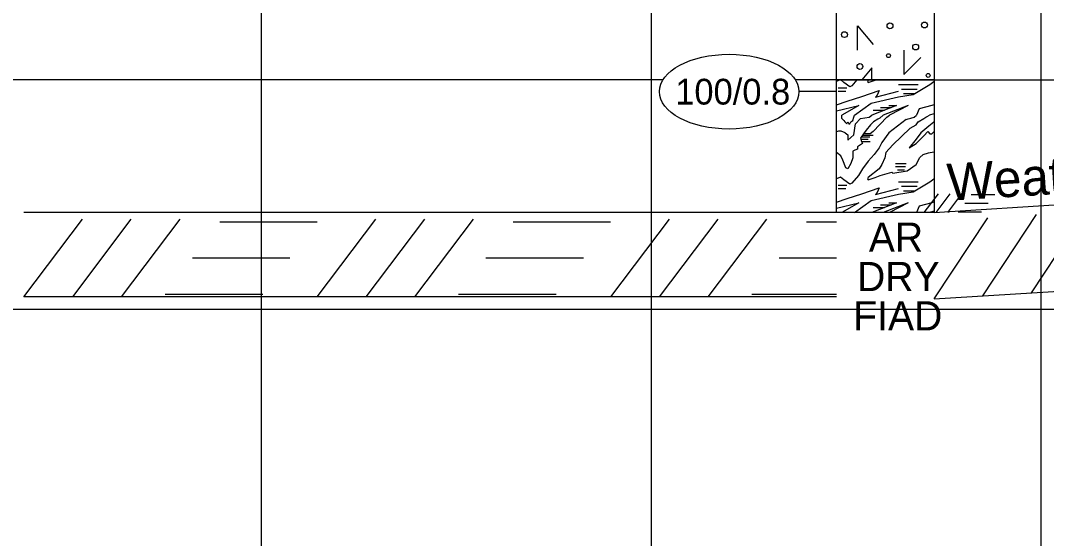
# Model space of a CAD drawing. Extents: x 278618 to 280654, y 171155 to 171855.
# Drawn here: x 280460.51 to 280486.82, y 171231.86 to 171245.16 of the extents above; entities that cross this region are included whole.
import ezdxf

# ---------------------------------------------------------------- set-up
doc = ezdxf.new("R2010")
doc.units = 0
for name, color, linetype in [('Prop Road Sect_ Boring - Material (Outline)', 7, 'Continuous'), ('Prop Road Sect_ Boring - Peripheral (HR Indicator)', 7, 'Continuous'), ('Prop Road Sect_ Boring - Peripheral (SPT Oval + Leader)', 7, 'Continuous'), ('Prop Road Sect_ Boring - Peripheral (SPT Tx)', 7, 'Continuous'), ('Prop Road Sect_ Material - Contact (General - Major)', 7, 'Continuous'), ('Prop Road Sect_ Material - Tx (Composite Desc)', 7, 'Continuous'), ('Prop Strc Sect_ Grid - minor', 7, 'Continuous'), ('Water Mark (Dry) Cell', 7, 'Continuous')]:
    doc.layers.add(name, color=color, linetype=linetype)

msp = doc.modelspace()

# ---------------------------------------------------------------- linework, layer by layer
at = {"layer": 'Prop Road Sect_ Boring - Material (Outline)'}
for p, q in [((280481.523, 171243.633), (280481.439, 171243.59)), ((280481.523, 171243.633), (280481.439, 171243.59)), ((280481.628, 171243.569), (280481.544, 171243.633)), ((280481.628, 171243.569), (280481.544, 171243.633)), ((280483.939, 171243.591), (280483.937, 171243.59)), ((280483.939, 171243.591), (280483.937, 171243.59)), ((280481.478, 171243.428), (280481.703, 171243.428)), ((280481.478, 171243.428), (280481.703, 171243.428)), ((280481.478, 171243.344), (280481.678, 171243.344)), ((280481.478, 171243.344), (280481.678, 171243.344)), ((280483.028, 171243.513), (280483.528, 171243.513)), ((280483.028, 171243.513), (280483.528, 171243.513)), ((280483.103, 171243.4), (280483.503, 171243.4)), ((280483.103, 171243.4), (280483.503, 171243.4)), ((280483.153, 171243.288), (280483.428, 171243.288)), ((280483.153, 171243.288), (280483.428, 171243.288)), ((280481.439, 171242.837), (280482.008, 171242.974)), ((280481.439, 171242.837), (280482.008, 171242.974)), ((280482.008, 171242.974), (280481.578, 171242.73)), ((280482.008, 171242.974), (280481.578, 171242.73)), ((280482.979, 171242.977), (280482.339, 171242.73)), ((280482.979, 171242.977), (280482.339, 171242.73)), ((280482.378, 171242.856), (280482.664, 171242.856)), ((280482.378, 171242.856), (280482.664, 171242.856)), ((280482.562, 171242.924), (280482.842, 171242.924)), ((280482.562, 171242.924), (280482.842, 171242.924)), ((280483.274, 171242.977), (280482.634, 171242.73)), ((280483.274, 171242.977), (280482.634, 171242.73)), ((280482.779, 171242.977), (280482.979, 171242.977)), ((280482.779, 171242.977), (280482.979, 171242.977)), ((280483.274, 171242.977), (280482.796, 171242.73)), ((280483.274, 171242.977), (280482.796, 171242.73)), ((280483.937, 171242.995), (280483.939, 171242.996)), ((280483.937, 171242.995), (280483.939, 171242.996)), ((280483.937, 171242.837), (280483.939, 171242.838)), ((280483.937, 171242.837), (280483.939, 171242.838)), ((280481.878, 171242.674), (280481.899, 171242.73)), ((280481.878, 171242.674), (280481.899, 171242.73)), ((280482.278, 171242.674), (280482.339, 171242.73)), ((280482.278, 171242.674), (280482.339, 171242.73)), ((280482.728, 171242.674), (280482.796, 171242.73)), ((280482.728, 171242.674), (280482.796, 171242.73)), ((280483.937, 171242.76), (280483.824, 171242.73)), ((280483.937, 171242.76), (280483.824, 171242.73)), ((280483.939, 171242.301), (280483.937, 171242.3)), ((280483.939, 171242.301), (280483.937, 171242.3)), ((280482.061, 171242.117), (280482.246, 171242.117)), ((280482.061, 171242.117), (280482.246, 171242.117)), ((280482.077, 171242.172), (280482.292, 171242.172)), ((280482.077, 171242.172), (280482.292, 171242.172)), ((280482.078, 171242.055), (280482.303, 171242.055)), ((280482.078, 171242.055), (280482.303, 171242.055)), ((280482.108, 171242.219), (280482.376, 171242.219)), ((280482.108, 171242.219), (280482.376, 171242.219)), ((280481.546, 171241.684), (280481.439, 171241.77)), ((280481.546, 171241.684), (280481.439, 171241.77)), ((280483.939, 171241.768), (280483.937, 171241.77)), ((280483.939, 171241.768), (280483.937, 171241.77)), ((280482.953, 171241.493), (280483.228, 171241.493)), ((280482.953, 171241.493), (280483.228, 171241.493)), ((280482.953, 171241.409), (280483.203, 171241.409)), ((280482.953, 171241.409), (280483.203, 171241.409)), ((280483.003, 171241.324), (280483.178, 171241.324)), ((280483.003, 171241.324), (280483.178, 171241.324)), ((280483.028, 171241.015), (280483.528, 171241.015)), ((280483.028, 171241.015), (280483.528, 171241.015)), ((280483.939, 171241.094), (280483.937, 171241.092)), ((280483.939, 171241.094), (280483.937, 171241.092)), ((280481.478, 171240.93), (280481.703, 171240.93)), ((280481.478, 171240.93), (280481.703, 171240.93)), ((280481.478, 171240.847), (280481.678, 171240.847)), ((280481.478, 171240.847), (280481.678, 171240.847)), ((280483.103, 171240.903), (280483.503, 171240.903)), ((280483.103, 171240.903), (280483.503, 171240.903)), ((280483.153, 171240.79), (280483.428, 171240.79)), ((280483.153, 171240.79), (280483.428, 171240.79)), ((280481.439, 171240.34), (280482.008, 171240.477)), ((280481.439, 171240.34), (280482.008, 171240.477)), ((280482.008, 171240.477), (280481.578, 171240.233)), ((280482.008, 171240.477), (280481.578, 171240.233)), ((280482.979, 171240.479), (280482.339, 171240.233)), ((280482.979, 171240.479), (280482.339, 171240.233)), ((280482.562, 171240.427), (280482.842, 171240.427)), ((280482.562, 171240.427), (280482.842, 171240.427)), ((280483.274, 171240.479), (280482.634, 171240.233)), ((280483.274, 171240.479), (280482.634, 171240.233)), ((280482.779, 171240.479), (280482.979, 171240.479)), ((280482.779, 171240.479), (280482.979, 171240.479)), ((280483.274, 171240.479), (280482.796, 171240.233)), ((280483.274, 171240.479), (280482.796, 171240.233)), ((280483.937, 171240.497), (280483.939, 171240.498)), ((280483.937, 171240.497), (280483.939, 171240.498)), ((280482.378, 171240.358), (280482.664, 171240.358)), ((280482.378, 171240.358), (280482.664, 171240.358)), ((280483.937, 171240.262), (280483.824, 171240.233)), ((280483.937, 171240.262), (280483.824, 171240.233)), ((280483.937, 171240.34), (280483.939, 171240.34)), ((280483.937, 171240.34), (280483.939, 171240.34))]:
    msp.add_line(p, q, dxfattribs=at)
for points in [[(280481.439, 171253.533), (280483.939, 171253.533), (280483.939, 171243.633), (280481.439, 171243.633)], [(280481.439, 171243.633), (280483.939, 171243.633), (280483.939, 171240.233), (280481.439, 171240.233)]]:
    msp.add_lwpolyline(points, close=True, dxfattribs=at)
for points in [[(280481.978, 171244.396), (280481.978, 171245.021), (280482.38, 171244.542)], [(280481.978, 171244.396), (280481.978, 171245.021), (280482.38, 171244.542)], [(280483.16, 171244.396), (280483.16, 171243.771), (280483.603, 171244.213)], [(280483.16, 171244.396), (280483.16, 171243.771), (280483.603, 171244.213)], [(280482.344, 171243.633), (280482.344, 171243.943), (280482.083, 171243.633)], [(280482.344, 171243.633), (280482.344, 171243.943), (280482.083, 171243.633)], [(280481.96, 171243.633), (280481.828, 171243.484), (280481.778, 171243.457), (280481.628, 171243.569)], [(280481.96, 171243.633), (280481.828, 171243.484), (280481.778, 171243.457), (280481.628, 171243.569)], [(280481.899, 171242.73), (280482.328, 171243.034), (280483.028, 171243.203), (280483.403, 171243.259), (280483.828, 171243.513), (280483.937, 171243.592)], [(280481.899, 171242.73), (280482.328, 171243.034), (280483.028, 171243.203), (280483.403, 171243.259), (280483.828, 171243.513), (280483.937, 171243.592)], [(280482.262, 171243.633), (280482.253, 171243.625), (280482.228, 171243.597), (280482.253, 171243.569), (280482.428, 171243.625), (280482.445, 171243.633)], [(280482.262, 171243.633), (280482.253, 171243.625), (280482.228, 171243.597), (280482.253, 171243.569), (280482.428, 171243.625), (280482.445, 171243.633)], [(280481.439, 171242.995), (280481.707, 171243.088), (280482.086, 171243.21), (280482.532, 171243.364), (280482.477, 171243.242), (280482.434, 171243.191), (280483.031, 171243.346)], [(280481.439, 171242.995), (280481.707, 171243.088), (280482.086, 171243.21), (280482.532, 171243.364), (280482.477, 171243.242), (280482.434, 171243.191), (280483.031, 171243.346)], [(280483.937, 171242.993), (280483.878, 171242.978), (280483.553, 171242.894), (280483.488, 171242.73)], [(280483.937, 171242.993), (280483.878, 171242.978), (280483.553, 171242.894), (280483.488, 171242.73)], [(280482.728, 171242.674), (280482.378, 171242.309), (280482.303, 171242.253), (280482.128, 171242.253), (280482.053, 171242.14), (280482.078, 171242.055), (280482.103, 171241.999), (280481.978, 171241.915), (280481.978, 171241.859), (280481.978, 171241.859), (280481.903, 171241.83), (280481.853, 171241.803), (280481.853, 171241.634), (280481.803, 171241.493), (280481.728, 171241.353), (280481.678, 171241.38), (280481.603, 171241.578), (280481.546, 171241.684)], [(280482.728, 171242.674), (280482.378, 171242.309), (280482.303, 171242.253), (280482.128, 171242.253), (280482.053, 171242.14), (280482.078, 171242.055), (280482.103, 171241.999), (280481.978, 171241.915), (280481.978, 171241.859), (280481.978, 171241.859), (280481.903, 171241.83), (280481.853, 171241.803), (280481.853, 171241.634), (280481.803, 171241.493), (280481.728, 171241.353), (280481.678, 171241.38), (280481.603, 171241.578), (280481.546, 171241.684)], [(280481.628, 171242.59), (280481.578, 171242.647), (280481.578, 171242.73)], [(280481.628, 171242.59), (280481.578, 171242.647), (280481.578, 171242.73)], [(280481.628, 171242.59), (280481.653, 171242.562), (280481.703, 171242.505), (280481.728, 171242.562), (280481.753, 171242.505), (280481.778, 171242.505), (280481.803, 171242.562), (280481.853, 171242.59), (280481.878, 171242.674)], [(280481.628, 171242.59), (280481.653, 171242.562), (280481.703, 171242.505), (280481.728, 171242.562), (280481.753, 171242.505), (280481.778, 171242.505), (280481.803, 171242.562), (280481.853, 171242.59), (280481.878, 171242.674)], [(280483.228, 171242.618), (280482.778, 171242.28), (280482.603, 171242.028), (280482.528, 171241.887), (280482.403, 171241.718), (280482.253, 171241.549), (280482.103, 171241.353), (280482.003, 171241.184), (280481.828, 171240.987), (280481.778, 171240.959), (280481.628, 171241.072)], [(280483.228, 171242.618), (280482.778, 171242.28), (280482.603, 171242.028), (280482.528, 171241.887), (280482.403, 171241.718), (280482.253, 171241.549), (280482.103, 171241.353), (280482.003, 171241.184), (280481.828, 171240.987), (280481.778, 171240.959), (280481.628, 171241.072)], [(280481.657, 171242.274), (280481.728, 171242.224), (280481.728, 171242.084), (280481.878, 171242.224), (280481.928, 171242.505), (280482.053, 171242.647), (280482.278, 171242.674)], [(280481.657, 171242.274), (280481.728, 171242.224), (280481.728, 171242.084), (280481.878, 171242.224), (280481.928, 171242.505), (280482.053, 171242.647), (280482.278, 171242.674)], [(280482.634, 171242.73), (280482.547, 171242.65), (280482.499, 171242.627), (280482.387, 171242.555), (280482.313, 171242.479), (280482.199, 171242.342), (280482.128, 171242.253)], [(280482.634, 171242.73), (280482.547, 171242.65), (280482.499, 171242.627), (280482.387, 171242.555), (280482.313, 171242.479), (280482.199, 171242.342), (280482.128, 171242.253)], [(280483.228, 171242.618), (280483.276, 171242.637), (280483.346, 171242.652), (280483.432, 171242.679), (280483.488, 171242.73)], [(280483.228, 171242.618), (280483.276, 171242.637), (280483.346, 171242.652), (280483.432, 171242.679), (280483.488, 171242.73)], [(280483.937, 171242.549), (280483.803, 171242.449), (280483.603, 171242.28), (280483.478, 171242.112), (280483.303, 171241.887), (280483.478, 171241.999), (280483.678, 171242.197), (280483.778, 171242.309), (280483.828, 171242.253), (280483.878, 171242.253), (280483.937, 171242.305)], [(280483.937, 171242.549), (280483.803, 171242.449), (280483.603, 171242.28), (280483.478, 171242.112), (280483.303, 171241.887), (280483.478, 171241.999), (280483.678, 171242.197), (280483.778, 171242.309), (280483.828, 171242.253), (280483.878, 171242.253), (280483.937, 171242.305)], [(280483.328, 171242.393), (280483.478, 171242.478), (280483.528, 171242.562), (280483.678, 171242.647), (280483.728, 171242.674)], [(280483.328, 171242.393), (280483.478, 171242.478), (280483.528, 171242.562), (280483.678, 171242.647), (280483.728, 171242.674)], [(280483.728, 171242.674), (280483.761, 171242.692), (280483.824, 171242.73)], [(280483.728, 171242.674), (280483.761, 171242.692), (280483.824, 171242.73)], [(280481.657, 171242.274), (280481.559, 171242.323), (280481.492, 171242.323), (280481.439, 171242.3)], [(280481.657, 171242.274), (280481.559, 171242.323), (280481.492, 171242.323), (280481.439, 171242.3)], [(280483.328, 171242.393), (280482.878, 171241.972), (280482.703, 171241.774), (280482.678, 171241.634), (280482.603, 171241.465), (280482.528, 171241.353), (280482.253, 171241.128), (280482.228, 171241.099), (280482.253, 171241.072), (280482.428, 171241.128), (280482.553, 171241.184), (280482.853, 171241.268), (280482.878, 171241.24), (280483.253, 171241.297), (280483.478, 171241.465), (280483.576, 171241.64)], [(280483.328, 171242.393), (280482.878, 171241.972), (280482.703, 171241.774), (280482.678, 171241.634), (280482.603, 171241.465), (280482.528, 171241.353), (280482.253, 171241.128), (280482.228, 171241.099), (280482.253, 171241.072), (280482.428, 171241.128), (280482.553, 171241.184), (280482.853, 171241.268), (280482.878, 171241.24), (280483.253, 171241.297), (280483.478, 171241.465), (280483.576, 171241.64)], [(280483.576, 171241.64), (280483.658, 171241.723), (280483.799, 171241.76), (280483.937, 171241.787)], [(280483.576, 171241.64), (280483.658, 171241.723), (280483.799, 171241.76), (280483.937, 171241.787)], [(280481.628, 171241.072), (280481.536, 171241.142), (280481.439, 171241.092)], [(280481.628, 171241.072), (280481.536, 171241.142), (280481.439, 171241.092)], [(280481.899, 171240.233), (280482.328, 171240.537), (280483.028, 171240.705), (280483.403, 171240.762), (280483.828, 171241.015), (280483.937, 171241.094)], [(280481.899, 171240.233), (280482.328, 171240.537), (280483.028, 171240.705), (280483.403, 171240.762), (280483.828, 171241.015), (280483.937, 171241.094)], [(280481.439, 171240.497), (280481.707, 171240.59), (280482.086, 171240.713), (280482.532, 171240.867), (280482.477, 171240.744), (280482.434, 171240.693), (280483.031, 171240.849)], [(280481.439, 171240.497), (280481.707, 171240.59), (280482.086, 171240.713), (280482.532, 171240.867), (280482.477, 171240.744), (280482.434, 171240.693), (280483.031, 171240.849)], [(280483.937, 171240.495), (280483.878, 171240.48), (280483.553, 171240.397), (280483.488, 171240.233)], [(280483.937, 171240.495), (280483.878, 171240.48), (280483.553, 171240.397), (280483.488, 171240.233)]]:
    msp.add_lwpolyline(points, dxfattribs=at)
for centre, radius in [((280482.809, 171245.023), 0.075), ((280482.809, 171245.023), 0.075), ((280483.694, 171245.045), 0.075), ((280483.694, 171245.045), 0.075), ((280481.64, 171244.797), 0.075), ((280481.64, 171244.797), 0.075), ((280483.468, 171244.478), 0.075), ((280483.468, 171244.478), 0.075), ((280482.77, 171244.257), 0.05), ((280482.77, 171244.257), 0.05), ((280482.038, 171243.979), 0.075), ((280482.038, 171243.979), 0.075), ((280483.788, 171243.75), 0.05), ((280483.788, 171243.75), 0.05)]:
    msp.add_circle(centre, radius, dxfattribs=at)
at = {"layer": 'Prop Road Sect_ Boring - Peripheral (HR Indicator)'}
for p, q in [((280483.689, 171240.233), (280484.05, 171240.711)), ((280483.989, 171240.233), (280484.35, 171240.711)), ((280484.289, 171240.233), (280484.65, 171240.711)), ((280484.895, 171240.695), (280485.495, 171240.695)), ((280484.727, 171240.472), (280485.327, 171240.472)), ((280484.559, 171240.249), (280485.159, 171240.249))]:
    msp.add_line(p, q, dxfattribs=at)
at = {"layer": 'Prop Road Sect_ Boring - Peripheral (SPT Oval + Leader)'}
for q in [(280480.472, 171243.333), (280481.251, 171243.333), (280481.251, 171243.333)]:
    msp.add_line((280481.439, 171243.333), q, dxfattribs=at)
msp.add_ellipse((280478.683, 171243.333), major_axis=(1.788, 0), ratio=0.536928, dxfattribs=at)
at = {"layer": 'Prop Road Sect_ Material - Contact (General - Major)'}
for p, q in [((280476.984, 171243.633), (280460.325, 171243.633)), ((280481.439, 171243.633), (280480.382, 171243.633)), ((280483.939, 171243.633), (280521.694, 171243.633)), ((280483.939, 171240.233), (280520.981, 171242.554)), ((280483.939, 171238.014), (280525.439, 171240.614)), ((280481.439, 171240.233), (280460.599, 171240.233)), ((280485.187, 171238.092), (280486.563, 171240.176)), ((280486.434, 171238.17), (280487.811, 171240.254)), ((280460.599, 171238.067), (280462.102, 171240.061)), ((280461.849, 171238.067), (280463.352, 171240.061)), ((280463.099, 171238.067), (280464.602, 171240.061)), ((280468.122, 171238.067), (280469.626, 171240.061)), ((280469.372, 171238.067), (280470.876, 171240.061)), ((280470.622, 171238.067), (280472.126, 171240.061)), ((280475.646, 171238.067), (280477.15, 171240.061)), ((280476.896, 171238.067), (280478.4, 171240.061)), ((280478.146, 171238.067), (280479.65, 171240.061)), ((280483.939, 171238.014), (280485.316, 171240.098)), ((280481.439, 171238.067), (280460.599, 171238.067))]:
    msp.add_line(p, q, dxfattribs=at)
for points in [[(280465.621, 171239.992), (280468.121, 171239.992)], [(280473.145, 171239.992), (280475.645, 171239.992)], [(280480.669, 171239.992), (280481.439, 171239.992)], [(280464.921, 171239.064), (280467.421, 171239.064)], [(280472.445, 171239.064), (280474.945, 171239.064)], [(280479.969, 171239.064), (280481.439, 171239.064)], [(280464.221, 171238.136), (280466.721, 171238.136)], [(280471.745, 171238.136), (280474.245, 171238.136)], [(280479.269, 171238.136), (280481.439, 171238.136)]]:
    msp.add_lwpolyline(points, dxfattribs=at)
at = {"layer": 'Prop Strc Sect_ Grid - minor'}
for p, q in [((280466.689, 171188.859), (280466.689, 171293.859)), ((280476.689, 171188.859), (280476.689, 171293.859)), ((280486.689, 171188.859), (280486.689, 171293.859)), ((280586.689, 171237.743), (280436.689, 171237.743))]:
    msp.add_line(p, q, dxfattribs=at)

# ---------------------------------------------------------------- texts
at = {"layer": 'Prop Road Sect_ Boring - Peripheral (SPT Tx)'}
msp.add_text('100/0.8', height=0.6612, dxfattribs=at).set_placement((280477.301, 171243.002))
at = {"layer": 'Prop Road Sect_ Material - Tx (Composite Desc)'}
msp.add_text('Weathered Rock:', height=0.95, rotation=3.5849, dxfattribs=at).set_placement((280484.304, 171240.531))
at = {"layer": 'Water Mark (Dry) Cell'}
for s, p in [('AR', (280482.266, 171239.222)), ('DRY', (280481.964, 171238.212)), ('FIAD', (280481.867, 171237.203))]:
    msp.add_text(s, height=0.75, dxfattribs=at).set_placement(p)

doc.saveas('drawing.dxf')
